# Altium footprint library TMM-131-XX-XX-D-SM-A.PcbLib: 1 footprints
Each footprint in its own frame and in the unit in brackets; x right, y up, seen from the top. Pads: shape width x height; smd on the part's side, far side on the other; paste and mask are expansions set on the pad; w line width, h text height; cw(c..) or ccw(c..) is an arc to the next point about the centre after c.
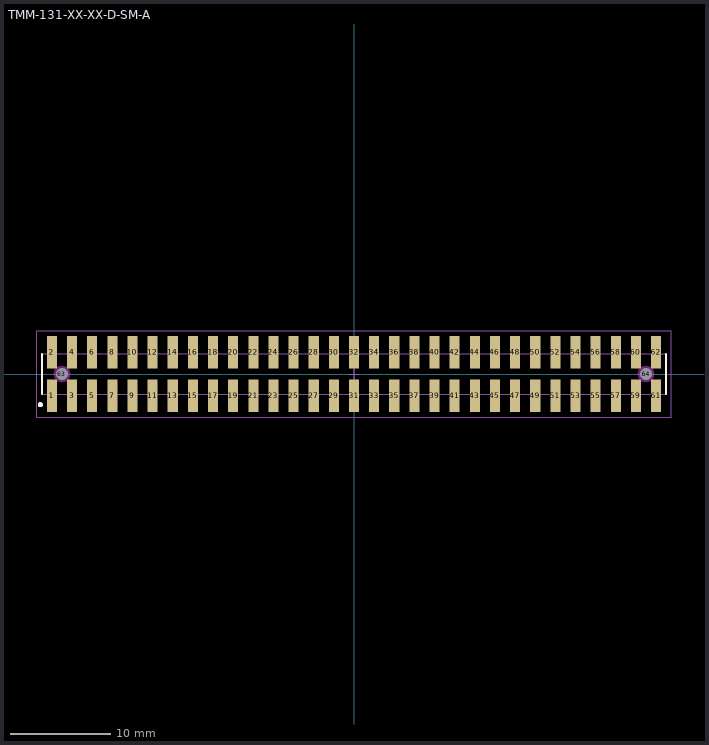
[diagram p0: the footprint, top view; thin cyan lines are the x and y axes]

## TMM-131-XX-XX-D-SM-A [mm] "2.00mm pitch, 62 pin, terminal strip; double row, w/alignment pins, SMT"
height 2.77
pads (64):
  rect 1x3.2 smd mask+0: 1(-30,-2.15) 2(-30,2.15) 3(-28,-2.15) 4(-28,2.15) 5(-26,-2.15) 6(-26,2.15) 7(-24,-2.15) 8(-24,2.15) 9(-22,-2.15) 10(-22,2.15) 11(-20,-2.15) 12(-20,2.15) 13(-18,-2.15) 14(-18,2.15) 15(-16,-2.15) 16(-16,2.15) 17(-14,-2.15) 18(-14,2.15) 19(-12,-2.15) 20(-12,2.15) 21(-10,-2.15) 22(-10,2.15) 23(-8,-2.15) 24(-8,2.15) 25(-6,-2.15) 26(-6,2.15) 27(-4,-2.15) 28(-4,2.15) 29(-2,-2.15) 30(-2,2.15) 31(0,-2.15) 32(0,2.15) 33(2,-2.15) 34(2,2.15) 35(4,-2.15) 36(4,2.15) 37(6,-2.15) 38(6,2.15) 39(8,-2.15) 40(8,2.15) 41(10,-2.15) 42(10,2.15) 43(12,-2.15) 44(12,2.15) 45(14,-2.15) 46(14,2.15) 47(16,-2.15) 48(16,2.15) 49(18,-2.15) 50(18,2.15) 51(20,-2.15) 52(20,2.15) 53(22,-2.15) 54(22,2.15) 55(24,-2.15) 56(24,2.15) 57(26,-2.15) 58(26,2.15) 59(28,-2.15) 60(28,2.15) 61(30,-2.15) 62(30,2.15)
  round 1 hole 1.2 unplated mask+0: 63(-29,0) 64(29,0)
Top Overlay:
  circle w0.25: c-31.15,-3.05 r0.125
  lines w0.2: -31,-2 -31,2 ; 31,-2 31,2
Keep-Out Layer:
  pour cut-out: 29.807,0 29.779,0.209 29.699,0.403 29.57,0.571 29.403,0.699 29.209,0.779 29,0.807 28.791,0.779 28.596,0.699 28.429,0.571 28.301,0.403 28.22,0.209 28.193,0 28.22,-0.209 28.301,-0.403 28.429,-0.571 28.596,-0.699 28.791,-0.779 29,-0.807 29.209,-0.779 29.403,-0.699 29.57,-0.571 29.699,-0.403 29.779,-0.209
  pour cut-out: -28.193,0 -28.22,0.209 -28.301,0.403 -28.429,0.571 -28.596,0.699 -28.791,0.779 -29,0.807 -29.209,0.779 -29.403,0.699 -29.57,0.571 -29.699,0.403 -29.779,0.209 -29.807,0 -29.779,-0.209 -29.699,-0.403 -29.57,-0.571 -29.403,-0.699 -29.209,-0.779 -29,-0.807 -28.791,-0.779 -28.596,-0.699 -28.429,-0.571 -28.301,-0.403 -28.22,-0.209
Mechanical 12:
  lines w0.001: -31,-2 -31,2 31,2 31,-2 -31,-2
Mechanical 13:
  lines w0.1: -31,-2 -31,2 31,2 31,-2 -31,-2
  text ".Designator" at 0.127,-0.127 h1.52
Mechanical 15:
  lines w0.05: -0.5,0 0.5,0 ; 0,-0.5 0,0.5 ; -31.5,-4.3 -31.5,4.3 31.5,4.3 31.5,-4.3 -31.5,-4.3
